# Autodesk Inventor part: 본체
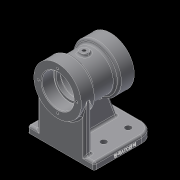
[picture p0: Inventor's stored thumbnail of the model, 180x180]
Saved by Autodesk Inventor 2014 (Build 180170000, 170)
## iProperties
Created: 2020-06
Part Number: 본체
Material: Generic
Document SubType Name: Modeling
Designer: kh
Density: 1 g/cm^3
Appearance: Default
Author: kh
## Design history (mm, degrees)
sketch "Sketch1"
  geometry: L1 (0, 49)-(90, 49); L2 (90, 49)-(90, -49); L3 (90, -49)-(0, -49); L4 (0, -49)-(0, 49); 2 further points
  constraints: 8 end point, 2 coincident, 2 parallel, 1 horizontal, 1 midpoint, 1 perpendicular
  dimensions: "d0" = 90 distance of L1.start L1.end; "d1" = 98 distance of L1.end L2.end
extrude "Extrusion1" new body sketch "Sketch1" distance "d2" = 10; taper "d3" = 0 deg
sketch "Sketch2"
  geometry: L1 (-73, 80)-(5, 80); L2 (5, 80)-(5, 115); L3 (5, 115)-(-17, 115); L4 (-17, 115)-(-17, 109); L5 (-17, 109)-(-51, 109); L6 (-51, 109)-(-51, 115); L7 (-51, 115)-(-73, 115); L8 (-73, 115)-(-73, 80); 1 further point
  constraints: 16 end point, 4 parallel, 2 vertical, 1 collinear, 1 horizontal, 1 perpendicular
  dimensions: "d4" = 70 diameter of L7 L1; "d5" = 58 diameter of L5 L1; "d6" = 78 distance between parallel lines of L2 L8; "d7" = 22 distance of L2.end L3.end; "d9" = 80 vertical distance of point (0, 0) L1.end; "d11" = 5 distance from line of L2 point (0, 0); "d78" = 22 distance of L6.end L7.end
revolve "Revolution1" sketch "Sketch2" stored, may be unused: angle "d10" = 90 deg
sketch "Sketch3"
  geometry: L1 (98, 0)-(0, 0) reference; L2 (14, 80)-(84, 80); L3 (84, 80)-(84, 0); L4 (84, 0)-(14, 0); L5 (14, 0)-(14, 80); C1 r 35 at (49, 80) reference; 3 further points
  constraints: 8 end point, 3 midpoint, 2 parallel, 1 coincident, 1 horizontal, 1 perpendicular
  dimensions: "d12" = 70 distance of L2.start L2.end
extrude "Extrusion2" join sketch "Sketch3" distance "d13" = 10; taper "d14" = 0 deg
sketch "Sketch4"
  geometry: L1 (-65.261, 45)-(-78, 10); L2 (0, 10)-(-90, 10) reference; L3 (-73, 45)-(-51, 45) reference; 1 further point
  constraints: 2 end point, 2 point on line
  dimensions: "d15" = 70 deg angle of L2 L1; "d16" = 12 distance of L1.end L2.end
feature "Rib1" sketch "Sketch4" dims "d17" = 1, "d18" = 10, "d19" = 0, "d20" = 0, "d21" = 1, "d22" = 1
workplane "Work Plane2"
  workplane "Work Plane1"
sketch "Sketch6"
  geometry: L1 (-17, -5)-(-17, 5) reference; L2 (-17, -5)-(17, -5) reference; L3 (17, -5)-(17, 5) reference; L4 (17, 5)-(-17, 5) reference; C1 r 6 at (0, 0); 2 further points
  constraints: 1 centre point, 1 horizontal alignment, 1 midpoint, 1 vertical alignment
  dimensions: "d31" = 12 diameter of C1
extrude "Extrusion3" join sketch "Sketch6" stored distance "d32" = 10; taper "d33" = 0 deg
sketch "Sketch5"
  geometry: L1 (5, 45)-(5, 115) reference; L2 (5, 80)-(-73, 80); L3 (-73, 45)-(-73, 115) reference; L4 (5, 103.5)-(-13, 103.5); L5 (-13, 103.5)-(-13, 100); L6 (-13, 100)-(-19, 100); L7 (-19, 100)-(-19, 103); L8 (-19, 103)-(-49, 103); L9 (-49, 103)-(-49, 100); L10 (-49, 100)-(-55, 100); L11 (-55, 100)-(-55, 103.5); L12 (-55, 103.5)-(-73, 103.5); L13 (5, 103.5)-(5, 80); L14 (-73, 103.5)-(-73, 80); 1 further point
  constraints: 24 end point, 6 collinear, 6 parallel, 4 perpendicular, 2 midpoint, 2 point on line
  dimensions: "d24" = 18 distance of L4.start L4.end; "d25" = 30 distance of L7.end L8.end; "d26" = 46 diameter of L8 L2; "d27" = 40 diameter of L6 L2; "d28" = 47 diameter of L4 L2
revolve "Revolution2" sketch "Sketch5" stored, may be unused: angle "d29" = 90 deg
hole "Hole1" diameter "d36" = 5.188; stored, may be unused: countersink angle "d40" = 90 deg, drill point angle "d42" = 118 deg; dims "d34" = 10, "d35" = 10, "d37" = 6, "d38" = 4, "d39" = 2, "d41" = 8
sketch "Sketch7"
  geometry: C1 r 23.5 at (0, 0) reference; 2 further points
  constraints: 1 vertical alignment
  dimensions: "d43" = 28.5 distance of point (0, 28.5) C1.centre
hole "Hole2" sketch "Sketch7" at (0, 28.5) diameter "d44" = 3.242; stored, may be unused: countersink angle "d48" = 90 deg, drill point angle "d50" = 118 deg; dims "d45" = 10, "d46" = 4, "d47" = 2, "d49" = 12
pattern_circular "Circular Pattern1" dims angle "d52" = 360 deg
workplane "Work Plane3"
mirror "Mirror1"
fillet "Fillet1" dims "d54" = 3
fillet "Fillet2" dims "d55" = 0.3
chamfer "Chamfer1" distance "d56" = 1; stored, may be unused: second distance "d57" = 2, angle "d58" = 45 deg
fillet "Fillet3" dims "d59" = 3
fillet "Fillet4" dims "d60" = 3
fillet "Fillet5" dims "d61" = 20
sketch "Sketch8"
  geometry: A1 r 20 centre (-70, -29) between (-90, -29) and (-70, -49) reference; A2 r 20 centre (-70, 29) between (-70, 49) and (-90, 29) reference; 1 further point
hole "Hole3" sketch "Sketch8" at (-70, -29), (-70, 29) diameter "d62" = 9; stored, may be unused: countersink angle "d66" = 90 deg, drill point angle "d68" = 118 deg; dims "d63" = 10, "d64" = 4, "d65" = 2, "d67" = 12
pattern_linear "Rectangular Pattern1" dims "d71" = 36
fillet "Fillet6" dims "d72" = 3
fillet "Fillet7" dims "d73" = 3
sketch "Sketch9"
  geometry: L1 (67, 0)-(0, 0) reference; L2 (-3, 7)-(-3, 0) reference; 1 further point
  constraints: 1 other
  dimensions: "d74" = 4 distance from line of L1 point (42, 4); "d75" = 45 distance from line of point (42, 4) L2
emboss "Emboss1" sketch "Sketch9" dims "d0" = 90, "d1" = 98, "d76" = 0.5, "d77" = 0
body "Solid1"
node "Projected Loop1"
other parameters: "d30" = 3
